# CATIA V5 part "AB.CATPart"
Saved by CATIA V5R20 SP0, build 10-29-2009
Part number: AB
Bounding box of the stored display mesh (mm): x -1.932 to 26.932, y -1.932 to 16.366, z 0 to 2
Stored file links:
  D:\IAO\22janv\AB.CATPart
  D:\IAO\14dec\ass_6barres.CATProduct
  D:\IAO\22janv\czortea.CATProduct
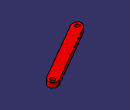
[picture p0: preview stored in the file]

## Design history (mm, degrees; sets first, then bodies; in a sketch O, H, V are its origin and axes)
External parameters (linked from other documents)
  External.epaisseur = 2 mm
Set1
  Plane1 "plan_ref": linked copy from another document
  Point1 "A": linked copy from another document
  Point2 "B": linked copy from another document
  Point3 "B": linked copy from another document
  Point4 "A": linked copy from another document
Body1 (main body)
  Sketch1 on Plane1, origin (0, 0, 0), H (1, 0, 0), V (0, 1, 0)
    construction line L1 (0, 0) -> (25, 14.4338)
    line L2 (-1, 1.7321) -> (24, 16.1658)
    line L3 (26, 12.7017) -> (1, -1.7321)
    arc A1 centre (25, 14.4338) radius 2 from (24, 16.1658) to (26, 12.7017) cw
    arc A2 centre (0, 0) radius 2 from (1, -1.7321) to (-1, 1.7321) cw
    reference projected point E1 (0, 0) from Point1
    reference projected point E2 (25, 14.4338) from Point2
    distance L1 L2 = 2 {= External.epaisseur}
    tangency: A1 L2, A2 L2, A1 L3, A2 L3
    concentricity: A2 E1, A1 E2
  Pad1: profile Sketch1, direction (0, 0, 1), length 2 {= External.epaisseur}
  Sketch2 on end face of Pad1, origin (15.1052, 7.1718, 2), H (1, 0, 0), V (0, 1, 0)
    point P1 (9.8948, 7.262)
    reference projected point E1 (9.8948, 7.262) from Point3
    coincidence: P1 E1
  Hole1: placed by Sketch2, at (25, 14.4338, 2) direction (0, 0, -1), diameter 2 {= External.epaisseur}, through (limit type 6)
  Sketch3 on end face of Pad1, origin (6.192, 1.6427, 2), H (1, 0, 0), V (0, 1, 0)
    point P1 (-6.192, -1.6427)
    reference projected point E1 (-6.192, -1.6427) from Point4
    coincidence: P1 E1
  Hole2: placed by Sketch3, at (0, 0, 2) direction (0, 0, -1), diameter 2 {= External.epaisseur}, through (limit type 6)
